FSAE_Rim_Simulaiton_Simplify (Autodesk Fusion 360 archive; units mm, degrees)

design "FSAE_Rim_Simulaiton_Simplify" references "Hexagon Socket Head Cap Screw DIN 912 - M4 x 0.7 x 16 Steel 4.6 Plain", "Hexagon Nut DIN 934 - M4 x 0.7 Steel 6 Plain"
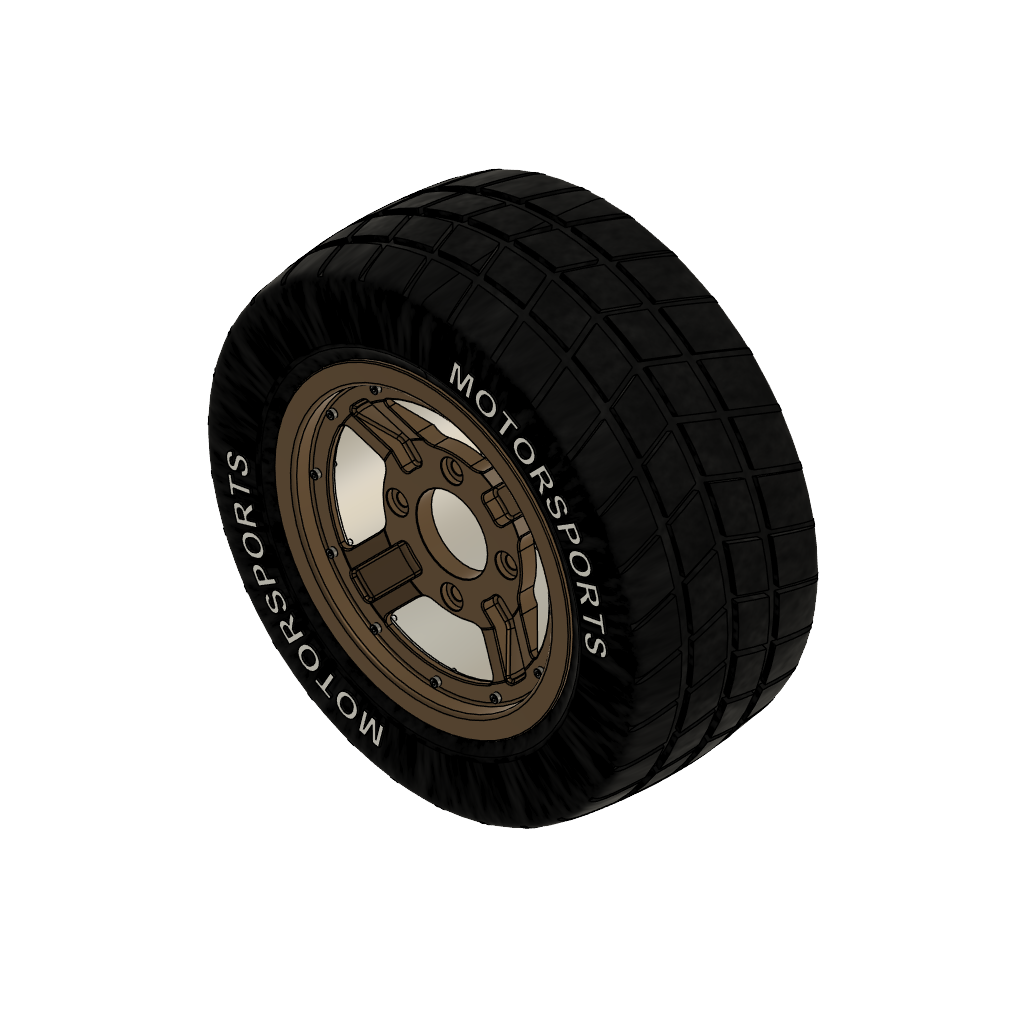
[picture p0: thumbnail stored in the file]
part number: 2026-07-27-09-56-27-671
part number: 2026-08-04-10-59-52-273
part number: 2026-08-04-10-59-52-284
part number: 2026-08-04-10-59-52-289
sketch "Sketch1" plane through (0, 0, 0) normal (1, 0, 0) x axis (0, 1, 0)
  line L1 (153.5, 0) -> (0, 0)
  line L2 (0, 119.5) -> (0, 104)
  line L3 (143.5, 124.5) -> (5, 124.5)
  line L4 (148.5, 134.75) -> (148.5, 129.5)
  line L5 (153.5, 138.25) -> (152, 138.25)
  line L6 (2.5, 119.5) -> (2.5, 104)
  line L7 (143.5, 122) -> (5, 122)
  line L8 (151, 134.75) -> (151, 129.5)
  line L9 (153.5, 135.75) -> (152, 135.75)
  line L10 (2.5, 104) -> (0, 104)
  line L11 (153.5, 135.75) -> (153.5, 138.25)
  arc A1 centre (152, 134.75) radius 3.5 clockwise from (148.5, 134.75) to (152, 138.25)
  arc A2 centre (143.5, 129.5) radius 5 clockwise from (148.5, 129.5) to (143.5, 124.5)
  arc A3 centre (5, 119.5) radius 5 clockwise from (0, 119.5) to (5, 124.5)
  arc A4 centre (5, 119.5) radius 2.5 clockwise from (2.5, 119.5) to (5, 122)
  arc A5 centre (143.5, 129.5) radius 7.5 clockwise from (151, 129.5) to (143.5, 122)
  arc A6 centre (152, 134.75) radius 1 clockwise from (151, 134.75) to (152, 135.75)
  point P1 (0, 0)
  point P2 (0, 0)
  point P4 (0, 104)
  point P3 (153.5, 0)
  point P7 (153.5, 138.25)
  point P6 (148.5, 124.5)
  point P5 (0, 124.5)
  coincident P1 P2
  horizontal L1
  perpendicular L1 L2
  perpendicular L2 L3
  perpendicular L3 L4
  perpendicular L4 L5
  vertical P1 P4
  vertical P3 P7
  tangent L4 A1
  tangent L5 A1
  coincident P6 L3
  coincident P6 L4
  tangent L3 A2
  tangent L4 A2
  coincident P5 L2
  coincident P5 L3
  tangent L2 A3
  tangent L3 A3
  equal A2 A3
  perpendicular L6 L10
  perpendicular L9 L11
  dimension "d1" distance P2 P3 = 153.5
  dimension "d2" = 208
  dimension "d3" = 249
  dimension "d4" = 276.5
  dimension "d5" distance P5 P6 = 148.5
  dimension "d6" radius A1 = 3.5
  dimension "d7" radius A2 = 5
  dimension "d8" = 2.5
revolve "Revolve1" sketch "Sketch1" AlongAngle 360 bodies "FSAE Rim Back"
sketch "Sketch2" plane through (0, 0, 0) normal (0, -1, 0) x axis (1, 0, 0)
  circle C1 centre (0, 0) radius 104
  circle C2 centre (0, 0) radius 119.5
  circle C3 centre (0, 0) radius 112
  circle C4 centre (0, 112) radius 2.15
  point P1 (0, 0)
  point P3 (0, 0)
  point P4 (0, 112)
  coincident P1 P3
  coincident C3 P4
  vertical P3 P4
  dimension "d10" diameter C3 = 224
  dimension "d11" diameter C4 = 4.3
extrude "Extrude1" cut sketch "Sketch2" profile of C4 to an object
circular_pattern "C-Pattern1" TotalAngle 360
canvas "Canvas1"
move "Move1"
sketch "Sketch4" plane through (0, 0, 0) normal (1, 0, 0) x axis (0, 1, 0)
  line L1 (14, 0) -> (0, 0)
  line L2 (14, 72.5) -> (14, 0)
  line L3 (-8, 102.5) -> (14, 72.5)
  line L4 (-8, 124.5) -> (-8, 102.5)
  line L5 (-23.5, 124.5) -> (-8, 124.5)
  line L6 (-23.5, 138) -> (-23.5, 124.5)
  line L7 (-28.25, 138) -> (-23.5, 138)
  line L8 (-28.25, 0) -> (-28.25, 138)
  line L9 (0, 0) -> (-28.25, 0)
  line L10 (-13, 118.1658) -> (-28.25, 119.5)
  line L11 (-13, 102.5) -> (-13, 118.1658)
  line L12 (0, 68.6338) -> (-13, 102.5)
  line L13 (0, 0) -> (0, 68.6338)
  point P1 (0, 0)
  point P2 (0, 0)
  point P11 (0, 0)
  point P12 (-28.25, 119.5)
  point P5 (-8, 102.5)
  point P14 (-13, 102.5)
  point P3 (14, 0)
  point P4 (14, 72.5)
  point P6 (-8, 124.5)
  point P8 (-23.5, 138)
  point P9 (-28.25, 138)
  coincident P1 P2
  horizontal L1
  perpendicular L1 L2
  perpendicular L1 L4
  perpendicular L4 L5
  perpendicular L5 L6
  perpendicular L6 L7
  coincident P1 P11
  collinear L1 L9
  perpendicular L8 L9
  coincident L8 P12
  parallel L8 L11
  vertical L13
  horizontal P5 P14
  dimension "d29" distance P2 P3 = 14
  dimension "d30" = 145
  dimension "d31" = 205
  dimension "d32" = 249
  dimension "d33" = 276
  dimension "d34" distance P4 P6 = 22
  dimension "d35" distance P6 P8 = 15.5
  dimension "d36" distance P8 P9 = 4.75
  dimension "d37" distance L4 L11 = 5
  dimension "d38" angle L12 L13 = 159
  dimension "d39" angle L10 L11 = 95
  dimension "d40" = 239
revolve "Revolve3" sketch "Sketch4" AlongAngle 360 bodies "FSAE Rim Front"
sketch "Sketch5" plane through (0, 0, 0) normal (0, -1, 0) x axis (1, 0, 0)
  circle C1 centre (0, 0) radius 68.6338
  circle C2 centre (0, 0) radius 33
  point P1 (0, 0)
  point P3 (0, 0)
  coincident P1 P3
  dimension "d42" diameter C2 = 66
extrude "Extrude2" cut sketch "Sketch5" profile of C2 to an object
sketch "Sketch6" plane through (0, 0, 0) normal (0, -1, 0) x axis (1, 0, 0)
  circle C1 centre (0, 0) radius 33
  circle C2 centre (0, 0) radius 68.6338
  circle C3 centre (0, 0) radius 50.8
  point P1 (0, 0)
  point P4 (0, 0)
  point P3 (0, 50.8)
  coincident P1 P4
  coincident P3 C3
  vertical P1 P3
  dimension "d45" diameter C3 = 101.6
hole "Hole1" HoleDiameter 10.5 TipAngle 180 CBDepth 5 CBDiameter 20
chamfer "Chamfer2" sketch "Sketch1" distance 0.5
circular_pattern "C-Pattern2" TotalAngle 360
sketch "Sketch7" plane through (0, -13, 0) normal (0, -1, 0) x axis (1, 0, 0)
  circle C1 centre (0, 0) radius 102.5
  circle C2 centre (0, 0) radius 118.1658
  circle C3 centre (0, 0) radius 112
  point P1 (0, 0)
  point P3 (0, 0)
  point P4 (0, 112)
  coincident P1 P3
  coincident C3 P4
  vertical P1 P4
  dimension "d53" diameter C3 = 224
hole "Hole2" HoleDiameter 4.3 TipAngle 180
circular_pattern "C-Pattern3" TotalAngle 360
fillet "Fillet1" radius 1 3 2
chamfer "Chamfer1" distance 0.5
form "Form1" bodies "Tire"
fillet "Fillet2" radius 5
sketch "Sketch8" plane through (0, 0, 0) normal (1, 0, 0) x axis (0, 1, 0)
  line L1 (47.5, 224.911) -> (47.5, 204.911)
  line L2 (57.5, 224.911) -> (47.5, 224.911)
  line L3 (57.5, 204.9943) -> (57.5, 224.911)
  line L4 (87.5, 224.911) -> (87.5, 204.2438)
  line L5 (97.5, 224.911) -> (87.5, 224.911)
  line L6 (97.5, 203.6595) -> (97.5, 224.911)
  line L7 (17.5, 224.911) -> (17.5, 203.6595)
  line L8 (7.5, 224.911) -> (17.5, 224.911)
  line L9 (7.5, 202.9073) -> (7.5, 224.911)
  arc A1 centre (57.5, -395.0057) radius 600 clockwise from (-46, 196) to (161, 196)
  point P2 (-46, 196)
  point P3 (161, 196)
  point P8 (57.5, 204.9943)
  point P9 (87.5, 204.2438)
  point P12 (97.5, 203.6595)
  point P13 (17.5, 203.6595)
  point P16 (7.5, 202.9073)
  point P5 (47.5, 204.911)
  point P1 (0, 0)
  point P6 (47.5, 224.911)
  point P7 (57.5, 224.911)
  horizontal P2 P3
  vertical L1
  perpendicular L1 L2
  midpoint A1 P8
  perpendicular L2 L3
  coincident A1 P9
  parallel L3 L4
  perpendicular L4 L5
  coincident A1 P12
  perpendicular L5 L6
  coincident A1 P13
  perpendicular L5 L7
  perpendicular L7 L8
  coincident A1 P16
  perpendicular L8 L9
  collinear L2 L8
  collinear L2 L5
  equal L2 L8
  equal L2 L5
  coincident A1 P5
  dimension "d68" radius A1 = 600
  dimension "d69" distance P1 P3 = 196
  dimension "d70" distance P1 P2 = 46
  dimension "d71" distance P1 P3 = 161
  dimension "d73" distance P6 P7 = 10
  dimension "d74" distance L1 L7 = 30
  dimension "d75" distance L3 L4 = 30
  dimension "d76" distance P5 P6 = 20
revolve "Revolve4" AlongAngle 360
revolve "Revolve5" sketch "Sketch8" AlongAngle 360
work_plane "WorkPlane1" AlongDistance 275 ExtraOffset 0
sketch "Sketch9" plane through (0, 0, 275) normal (0, 0, 1) x axis (1, 0, 0)
  line L1 (-48.7008, 53.5011) -> (0, -75.7953)
  line L2 (0, 197.5142) -> (-48.7008, 53.5011)
  line L3 (-43.392, 53.5917) -> (4.6791, -74.0329)
  line L4 (4.7365, 195.9124) -> (-43.392, 53.5917)
  line L5 (4.6791, -74.0329) -> (0, -75.7953)
  line L6 (0, 197.5142) -> (4.7365, 195.9124)
  perpendicular L3 L5
  perpendicular L2 L6
  dimension "d80" = 5
step "SurfaceExtend" extendDistance 125
extrude "Extrude3" cut sketch "Sketch9" to an object
circular_pattern "C-Pattern4" countU 30 TotalAngle 360
remove_body "RemoveBody1"
remove_body "RemoveBody2"
work_plane "WorkPlane2" AlongDistance -150 ExtraOffset 0
sketch "Sketch10" plane through (0, -150, 0) normal (0, 1, 0) x axis (1, 0, 0)
  circle C1 centre (0, 0) radius 157.5
  point P1 (0, 0)
  point P2 (0, 0)
  coincident P1 P2
  dimension "d88" diameter C1 = 315
  dimension "d89" Text1-Height = 20
extrude "Extrude4" sketch "Sketch10" blind 2
circular_pattern "C-Pattern5" TotalAngle 360
component_from_bodies "Body->Comp1"
component_from_bodies "Body->Comp2"
component_from_bodies "Body->Comp3"
sketch "Sketch1" plane through (0, -13, 0) normal (0, -1, 0) x axis (1, 0, 0)
  line L1 (0, 103.056) -> (0, 0)
  line L2 (103.056, 0) -> (0, 0)
  line L3 (72.8716, 72.8716) -> (0, 0)
  line L4 (88.3726, 53.0172) -> (60.1041, 24.7487)
  line L5 (53.0172, 88.3726) -> (24.7487, 60.1041)
  circle C1 centre (0, 0) radius 103.056
  circle C2 centre (0, 112) radius 2.15
  circle C3 centre (56, 96.9948) radius 2.15
  circle C4 centre (96.9948, 56) radius 2.15
  circle C5 centre (112, 0) radius 2.15
  circle C6 centre (96.9948, -56) radius 2.15
  circle C7 centre (56, -96.9948) radius 2.15
  circle C8 centre (0, -112) radius 2.15
  circle C9 centre (-56, -96.9948) radius 2.15
  circle C10 centre (-96.9948, -56) radius 2.15
  circle C11 centre (-112, 0) radius 2.15
  circle C12 centre (-96.9948, 56) radius 2.15
  circle C13 centre (-56, 96.9948) radius 2.15
  circle C14 centre (0, 0) radius 116.3331
  arc A1 centre (0, 0) radius 65 clockwise from (0, 65) to (65, 0)
  arc A2 centre (0, 0) radius 65 clockwise from (65, 0) to (0, 65)
  point P2 (0, 0)
  point P16 (0, 0)
  point P17 (0, 103.056)
  point P18 (103.056, 0)
  point P15 (0, 0)
  point P19 (0, 0)
  point P20 (72.8716, 72.8716)
  point P22 (24.7487, 60.1041)
  point P21 (60.1041, 24.7487)
  point P23 (53.0172, 88.3726)
  point P24 (88.3726, 53.0172)
  point P25 (0, 65)
  point P26 (65, 0)
  concentric C1 A1
  coincident P2 P16
  coincident C1 P17
  vertical L1
  coincident C1 P18
  perpendicular L1 L2
  coincident P15 P19
  coincident C1 P20
  coincident P22 A1
  coincident P21 A1
  coincident C1 P23
  coincident C1 P24
  coincident L1 P25
  coincident L2 P26
  concentric A1 A2
  dimension "d95" diameter A1 = 130
  dimension "d96" angle L1 L3 = 45
extrude "Extrude1" cut sketch "Sketch1" profile of C1 L1 L2 L4 L5 A1 to an object
circular_pattern "C-Pattern1" TotalAngle 360
sketch "Sketch2" plane through (0, -13, 0) normal (0, -1, 0) x axis (1, 0, 0)
  line L1 (72.8716, 72.8716) -> (0, 0)
  line L2 (65.9862, 82.9568) -> (25.8367, 42.8073)
  line L3 (82.9568, 65.9862) -> (42.8073, 25.8367)
  arc A1 centre (0, 0) radius 103.056 clockwise from (-53.0172, 88.3726) to (53.0172, 88.3726)
  arc A2 centre (0, 0) radius 103.056 clockwise from (53.0172, 88.3726) to (88.3726, 53.0172)
  arc A3 centre (0, 0) radius 103.056 clockwise from (88.3726, 53.0172) to (88.3726, -53.0172)
  arc A4 centre (0, 0) radius 103.056 clockwise from (88.3726, -53.0172) to (53.0172, -88.3726)
  arc A5 centre (0, 0) radius 103.056 clockwise from (53.0172, -88.3726) to (-53.0172, -88.3726)
  arc A6 centre (0, 0) radius 103.056 clockwise from (-53.0172, -88.3726) to (-88.3726, -53.0172)
  arc A7 centre (0, 0) radius 103.056 clockwise from (-88.3726, -53.0172) to (-88.3726, 53.0172)
  arc A8 centre (0, 0) radius 103.056 clockwise from (-88.3726, 53.0172) to (-53.0172, 88.3726)
  circle C1 centre (0, 112) radius 2.15
  circle C2 centre (56, 96.9948) radius 2.15
  circle C3 centre (96.9948, 56) radius 2.15
  circle C4 centre (112, 0) radius 2.15
  circle C5 centre (96.9948, -56) radius 2.15
  circle C6 centre (56, -96.9948) radius 2.15
  circle C7 centre (0, -112) radius 2.15
  circle C8 centre (-56, -96.9948) radius 2.15
  circle C9 centre (-96.9948, -56) radius 2.15
  circle C10 centre (-112, 0) radius 2.15
  circle C11 centre (-96.9948, 56) radius 2.15
  circle C12 centre (-56, 96.9948) radius 2.15
  circle C13 centre (0, 0) radius 116.3331
  circle C14 centre (0, 0) radius 50
  circle C15 centre (0, 0) radius 106
  point P23 (0, 0)
  point P25 (0, 0)
  point P27 (25.8367, 42.8073)
  point P28 (42.8073, 25.8367)
  point P29 (82.9568, 65.9862)
  point P30 (65.9862, 82.9568)
  parallel L1 L2
  parallel L1 L3
  coincident P23 P25
  concentric C14 C15
  coincident C14 P27
  coincident C14 P28
  coincident C15 P29
  coincident C15 P30
  dimension "d103" distance L1 L2 = 12
  dimension "d104" distance L1 L3 = 12 (= "d103")
  dimension "d105" diameter C14 = 100
  dimension "d106" diameter C15 = 212
extrude "Extrude2" cut sketch "Sketch2" profile of A2 L2 L3 C14 C15 to an object offset 2
fillet "Fillet1" radius 5
fillet "Fillet2" radius 10
fillet "Fillet3" radius 2
circular_pattern "C-Pattern2" TotalAngle 360
fillet "Fillet4" radius 15 5
chamfer "Chamfer1" sketch "Sketch1" distance 1
step "Screw1"
joint "Assemble" alignAngle 0 alignOffsetX 0 alignOffsetY 0 alignOffsetZ 0
step "Screw2"
joint "Assemble" alignAngle 0 alignOffsetX 0 alignOffsetY 0 alignOffsetZ 0
step "Screw3"
joint "Assemble" alignAngle 0 alignOffsetX 0 alignOffsetY 0 alignOffsetZ 0
step "Screw4"
joint "Assemble" alignAngle 0 alignOffsetX 0 alignOffsetY 0 alignOffsetZ 0
step "Screw5"
joint "Assemble" alignAngle 0 alignOffsetX 0 alignOffsetY 0 alignOffsetZ 0
step "Screw6"
joint "Assemble" alignAngle 0 alignOffsetX 0 alignOffsetY 0 alignOffsetZ 0
step "Screw7"
joint "Assemble" alignAngle 0 alignOffsetX 0 alignOffsetY 0 alignOffsetZ 0
step "Screw8"
joint "Assemble" alignAngle 0 alignOffsetX 0 alignOffsetY 0 alignOffsetZ 0
step "Screw9"
joint "Assemble" alignAngle 0 alignOffsetX 0 alignOffsetY 0 alignOffsetZ 0
step "Screw10"
joint "Assemble" alignAngle 0 alignOffsetX 0 alignOffsetY 0 alignOffsetZ 0
step "Screw11"
joint "Assemble" alignAngle 0 alignOffsetX 0 alignOffsetY 0 alignOffsetZ 0
step "Screw12"
joint "Assemble" alignAngle 0 alignOffsetX 0 alignOffsetY 0 alignOffsetZ 0
step "Nut13"
joint "Assemble" alignAngle 0 alignOffsetX 0 alignOffsetY 0 alignOffsetZ 0
step "Nut14"
joint "Assemble" alignAngle 0 alignOffsetX 0 alignOffsetY 0 alignOffsetZ 0
step "Nut15"
joint "Assemble" alignAngle 0 alignOffsetX 0 alignOffsetY 0 alignOffsetZ 0
step "Nut16"
joint "Assemble" alignAngle 0 alignOffsetX 0 alignOffsetY 0 alignOffsetZ 0
step "Nut17"
joint "Assemble" alignAngle 0 alignOffsetX 0 alignOffsetY 0 alignOffsetZ 0
step "Nut18"
joint "Assemble" alignAngle 0 alignOffsetX 0 alignOffsetY 0 alignOffsetZ 0
step "Nut19"
joint "Assemble" alignAngle 0 alignOffsetX 0 alignOffsetY 0 alignOffsetZ 0
step "Nut20"
joint "Assemble" alignAngle 0 alignOffsetX 0 alignOffsetY 0 alignOffsetZ 0
step "Nut21"
joint "Assemble" alignAngle 0 alignOffsetX 0 alignOffsetY 0 alignOffsetZ 0
step "Nut22"
joint "Assemble" alignAngle 0 alignOffsetX 0 alignOffsetY 0 alignOffsetZ 0
step "Nut23"
joint "Assemble" alignAngle 0 alignOffsetX 0 alignOffsetY 0 alignOffsetZ 0
step "Nut24"
joint "Assemble" alignAngle 0 alignOffsetX 0 alignOffsetY 0 alignOffsetZ 0
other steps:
base_feature "Base Feature1" bodies "FSAE Rim Back"
base_feature "Base Feature1" bodies "Tire"
base_feature "Base Feature1" bodies "FSAE Rim Front"
create_component "CreateComponent1"
reparent_decal "ReparentDecal1"
remove_body "RemoveBody3"
create_component "CreateComponent2"
reparent_decal "ReparentDecal2"
remove_body "RemoveBody4"
create_component "CreateComponent3"
reparent_decal "ReparentDecal3"
remove_body "RemoveBody5"
joint_origin "JointOrigin1"
joint_origin "JointOrigin2"
joint_origin "JointOrigin3"
joint_origin "JointOrigin4"
joint_origin "JointOrigin5"
joint_origin "JointOrigin6"
joint_origin "JointOrigin7"
joint_origin "JointOrigin8"
joint_origin "JointOrigin9"
joint_origin "JointOrigin10"
joint_origin "JointOrigin11"
joint_origin "JointOrigin12"
joint_origin "JointOrigin1"
joint_origin "JointOrigin2"
joint_origin "JointOrigin3"
joint_origin "JointOrigin4"
joint_origin "JointOrigin5"
joint_origin "JointOrigin6"
joint_origin "JointOrigin7"
joint_origin "JointOrigin8"
joint_origin "JointOrigin9"
joint_origin "JointOrigin10"
joint_origin "JointOrigin11"
joint_origin "JointOrigin12"
named bodies: "FSAE Rim Back", "FSAE Rim Front", "Tire"

design "Hexagon Nut DIN 934 - M4 x 0.7 Steel 6 Plain"
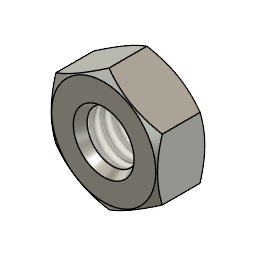
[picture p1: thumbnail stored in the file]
description: Hexagon Nut DIN 934 - M4 x 0.7
part number: DIN 934 - M4 x 0.7 Steel 6 Plain
parameter "adsk_nheig" = 3.2
parameter "adsk_maxdia" = 8.085
parameter "adsk_nomdia" = 4
parameter "adsk_waflat" = 7
parameter "adsk_chamang1" = 30
parameter "adsk_chamang2" = 30
parameter "adsk_beardia" = 6.86 (= "adsk_waflat * 0.98")
sketch "Sketch1" plane through (0, 0, 0) normal (0, 1, 0) x axis (1, 0, 0)
  line L1 (0, -3.2) -> (0, 0)
  line L2 (-3.43, 0) -> (-2, 0)
  line L3 (-4.0425, -0.3536) -> (-3.43, 0)
  line L4 (-4.0425, -2.8464) -> (-4.0425, -0.3536)
  line L5 (-3.43, -3.2) -> (-4.0425, -2.8464)
  line L6 (-2, -3.2) -> (-3.43, -3.2)
  line L7 (-2, 0) -> (-2, -3.2)
  point P3 (0, -3.2)
  point P1 (0, 0)
  point P2 (0, 0)
  point P10 (0, 0)
  point P5 (-3.43, 0)
  point P8 (-3.43, -3.2)
  vertical L1
  coincident L1 P3
  coincident P1 L1
  horizontal L2
  coincident P1 L2
  coincident P2 P10
  coincident P3 L6
  vertical P5 P8
  dimension "d121" = 4 (= "adsk_nomdia")
  dimension "d122" angle L2 L3 = 30 (= "adsk_chamang1")
  dimension "d123" angle L5 L6 = 30 (= "adsk_chamang2")
  dimension "d128" = 8.085 (= "adsk_maxdia")
  dimension "d172" = 6.86 (= "adsk_beardia")
  dimension "d179" distance L2 L6 = 3.2 (= "adsk_nheig")
revolve "Revolve1" sketch "Sketch1" AlongAngle 360
sketch "Sketch8" plane through (0, 0, 3.2) normal (0, 0, 1) x axis (1, 0, 0)
  line L1 (-3.5, 2.0228) -> (-3.5, -2.0228)
  circle C1 centre (0, 0) radius 2
  circle C2 centre (0, 0) radius 4.0425
  point P3 (-3.5, 2.0228)
  point P2 (-3.5, -2.0228)
  point P1 (0, 0)
  coincident P3 C2
  coincident P2 C2
  vertical L1
  dimension "d114" distance P1 L1 = 3.5 (= "adsk_waflat / 2")
extrude "Extrude5" cut sketch "Sketch8" profile of L1 C2 no distance stored
circular_pattern "C-Pattern2" TotalAngle 360
thread "Thread3" ThreadOffset 0 ThreadLength 10
sketch "Sketch12" plane through (0, 0, 0) normal (0, 1, 0) x axis (1, 0, 0)
  line L1 (0, 0) -> (-2, 0)
  line L2 (-2, 0) -> (-1.0762, -1.6)
  line L3 (0, -3.2) -> (-2, -3.2)
  line L4 (-2, -3.2) -> (-1.0762, -1.6)
  line L5 (0, -3.2) -> (0, 0)
  point P4 (-1.0762, -1.6)
  point P7 (-1.0762, -1.6)
  point P2 (-2, 0)
  point P5 (-2, -3.2)
  point P6 (0, -3.2)
  point P9 (0, -3.2)
  point P1 (0, 0)
  point P3 (0, 0)
  horizontal L1
  coincident P4 P7
  vertical P2 P5
  coincident P6 P9
  coincident P1 P3
  perpendicular L3 L5
  dimension "d169" angle L3 L4 = 60
  dimension "d177" distance P2 L5 = 2 (= "adsk_nomdia * 0.5")
  dimension "d178" angle L1 L2 = 60
revolve "Revolve3" sketch "Sketch12" AlongAngle 360
joint_origin "JointOrigin9" OffsetX 0 OffsetY 0 OffsetZ 0 AngleZ 0
joint_origin "JointOrigin10" OffsetX 0 OffsetY 0 OffsetZ 3.2 (= "adsk_nheig") AngleZ 0

design "Hexagon Socket Head Cap Screw DIN 912 - M4 x 0.7 x 16 Steel 4.6 Plain"
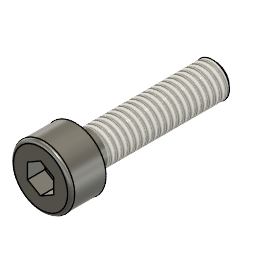
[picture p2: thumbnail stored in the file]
description: Hexagon Socket Head Cap Screw DIN 912 - M4 x 0.7 x 16
part number: DIN 912 - M4 x 0.7 x 16 Steel 4.6 Plain
parameter "adsk_nomlen" = 16
parameter "adsk_headh" = 4
parameter "adsk_headdia" = 7
parameter "adsk_nomdia" = 4
parameter "adsk_philwidth" = 3
parameter "adsk_phildepth" = 2
parameter "adsk_thrlen" = 14.25
parameter "adsk_startlen" = 0.4294
parameter "adsk_endpointdia" = 3.1412
sketch "Sketch1" plane through (0, 0, 0) normal (0, 1, 0) x axis (1, 0, 0)
  line L1 (-2, 16) -> (-2, 0)
  line L2 (0, 16) -> (-2, 16)
  line L3 (0, -4) -> (0, 16)
  line L4 (-3.5, 0) -> (-2, 0)
  line L5 (-3.5, -4) -> (-3.5, 0)
  line L6 (0, -4) -> (-3.5, -4)
  point P1 (0, 0)
  point P4 (0, 16)
  point P7 (0, -4)
  point P5 (-3.5, 0)
  perpendicular L1 L2
  collinear P1 P4 P7
  perpendicular L1 L4
  coincident P1 L4
  vertical L3
  coincident L3 P7
  perpendicular L3 L6
  dimension "d101" distance P1 L2 = 16 (= "adsk_nomlen")
  dimension "d102" distance P5 L6 = 4 (= "adsk_headh")
  dimension "d109" = 7 (= "adsk_headdia")
  dimension "d110" = 4 (= "adsk_nomdia")
revolve "Revolve1" sketch "Sketch1" AlongAngle 360
work_plane "WorkPlane1" AlongDistance 4 (= "adsk_headh")
sketch "Sketch6" plane through (0, 0, 4) normal (0, 0, 1) x axis (1, 0, 0)
  line L1 (1.5, -0.866) -> (0, -1.7321)
  line L2 (1.5, 0.866) -> (1.5, -0.866)
  line L3 (0, 1.7321) -> (1.5, 0.866)
  line L4 (-1.5, 0.866) -> (0, 1.7321)
  line L5 (-1.5, -0.866) -> (-1.5, 0.866)
  line L6 (0, -1.7321) -> (-1.5, -0.866)
  point P1 (0, 0)
  point P8 (0, 0)
  coincident P1 P8
  vertical L2
  dimension "d111" distance L2 L5 = 3 (= "adsk_philwidth")
extrude "Extrude1" cut sketch "Sketch6" no distance stored
extrude "Extrude2" cut of existing geometry no distance stored taper -85
thread "Thread3" ThreadOffset 0 ThreadLength 14.25 (= "min(adsk_thrlen; adsk_nomlen - 0.001 mm)")
fillet "Fillet4" radius 0.4 (= "adsk_nomdia * 0.1")
sketch "Sketch7" plane through (0, 0, 0) normal (0, 1, 0) x axis (1, 0, 0)
  line L1 (-2.04, 15.5706) -> (-2.04, 16)
  line L2 (-1.5706, 16) -> (-2.04, 15.5706)
  line L3 (0, -4) -> (0, 16)
  line L4 (0, 16) -> (-2.04, 16)
  point P5 (0, 16)
  point P7 (0, 16)
  point P4 (-1.5706, 16)
  point P3 (-2.04, 15.5706)
  coincident P5 P7
  perpendicular L3 L4
  coincident P4 L4
  perpendicular L1 L4
  dimension "d104" distance P4 L3 = 1.5706 (= "adsk_endpointdia / 2")
  dimension "d105" distance L1 P7 = 2.04 (= "adsk_nomdia * 0.51")
  dimension "d106" distance P3 L4 = 0.4294 (= "adsk_startlen")
revolve "Revolve3" sketch "Sketch7" AlongAngle 360
joint_origin "JointOrigin2" OffsetX 0 OffsetY 0 OffsetZ 0 AngleZ 0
